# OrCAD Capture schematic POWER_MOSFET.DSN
size A
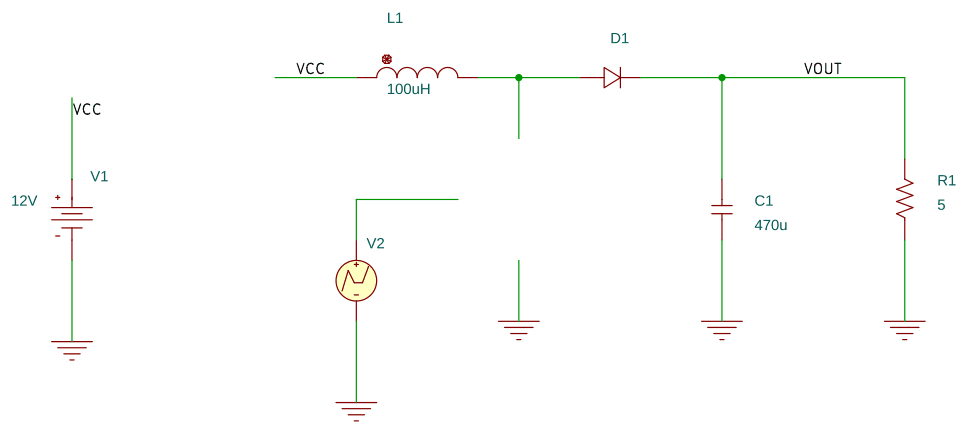
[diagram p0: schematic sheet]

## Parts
C1  470u  [cap196]
D1  Dbreak
L1  100uH  [DISC350x175LS200x100034]
R1  5  [AXRC05]
V1  VDC
V2  VPWL_GENERIC

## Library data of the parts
C1 = C
D1 = Dbreak
L1 = L
R1 = R
V1 = VDC: DC: 12V
V2 = VPWL_GENERIC: AppProp: Forever_reps$POINTS_TYPE_PWL$0$0; FIRST_NPAIRS: 0 5 6.99u 5 7u 0 12.99u 0 13u 5; PSpiceTemplate: V^@REFDES %+ %- ?DC|DC @DC| ?AC|AC @AC| PWL ?TSF|TIME_SCALE_FACTOR=@TSF| ?VSF|VALUE_SCALE_FACTOR=@VSF| \n+ REPEAT FOREVER  \n+ @FIRST_NPAIRS ?SECOND_NPAIRS|\n+ @SECOND_NPAIRS ?THIRD_NPAIRS/\n+ @THIRD_NPAIRS/| \n+ ENDREPEAT

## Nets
VCC: L1.1 V1.0(+)
0: C1.1 R1.1 V1.1(-) V2.2(-)
VOUT: C1.2 D1.1(2) R1.2
N00229: D1.0(1) L1.2

Not connected (* = marked no-connect by the designer): V2 1(+)
